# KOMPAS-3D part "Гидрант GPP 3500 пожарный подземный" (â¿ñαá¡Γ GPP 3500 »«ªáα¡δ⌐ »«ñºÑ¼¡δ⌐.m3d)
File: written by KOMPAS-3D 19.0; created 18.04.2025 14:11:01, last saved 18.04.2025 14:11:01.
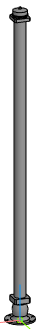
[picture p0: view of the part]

Document properties: Полное имя файла: E:\Dendor Работа Сачек\3D для проекитирвщиков\11.1 Тип GPP. Гидрант пожарный подземный\stp_Тип GPP. 750-6000 Гидрант пожарный подземный\Гидрант GPP 3500 пожарный подземный.m3d

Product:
- Part/product: Гидрант GPP 3500 пожарный подземный

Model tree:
1. Операция без истории:1  (labels: Гидрант GPP 3500 пожарный подземный)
